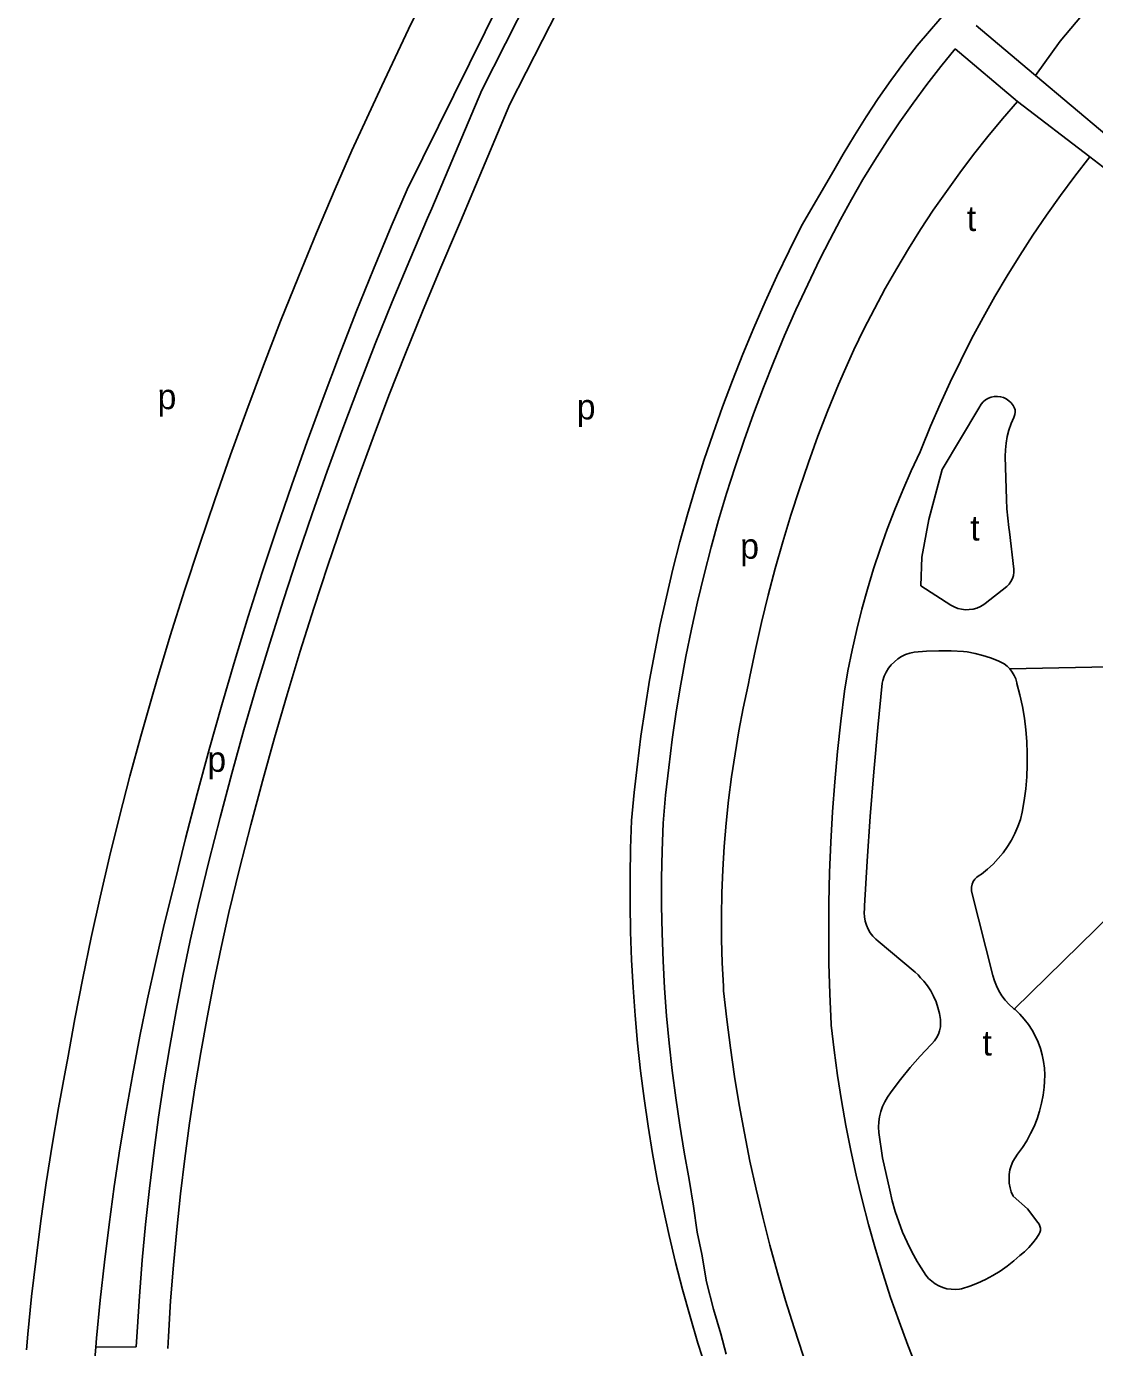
# Model space of a CAD drawing. Extents: x 161494 to 163033, y 383688 to 384862.
# Drawn here: x 161508.7 to 161678.1, y 384170.2 to 384379.7 of the extents above; entities that cross this region are included whole.
import ezdxf

# ---------------------------------------------------------------- set-up
doc = ezdxf.new("R2010")
doc.units = 0
doc.layers.add('BLT_Basislijn', color=7, linetype='Continuous')
doc.layers.add('BLT_Centroide', color=7, linetype='Continuous')

msp = doc.modelspace()

# ---------------------------------------------------------------- linework, layer by layer
at = {"layer": 'BLT_Basislijn'}
for p, q in [((161627.72, 384461.69), (161580.87, 384369.61)), ((161592.77, 384381.97), (161590.5, 384377.51)), ((161659.3, 384379.87), (161668.38, 384372.17)), ((161590.5, 384377.51), (161585.32, 384367.34)), ((161655.95, 384376.15), (161665.86, 384367.81)), ((161668.71, 384371.89), (161668.38, 384372.17)), ((161680, 384362.41), (161668.71, 384371.89)), ((161580.87, 384369.61), (161572.96, 384350.8)), ((161585.32, 384367.34), (161577.52, 384348.75)), ((161677.29, 384359), (161665.86, 384367.81)), ((161691.03, 384348.41), (161677.29, 384359)), ((161636.69, 384356.84), (161631.59, 384348.06)), ((161653.88, 384309.4), (161659.72, 384319.16)), ((161660.08, 384319.79), (161659.72, 384319.16)), ((161663.89, 384311.49), (161664.12, 384304.65)), ((161651.76, 384301.5), (161653.88, 384309.4)), ((161665.26, 384293.63), (161664.6, 384299.56)), ((161655.27, 384287.92), (161650.51, 384290.96)), ((161660.71, 384288.19), (161664.16, 384290.86)), ((161664.61, 384277.82), (161691.09, 384278.37)), ((161658.57, 384242.55), (161661.91, 384229.19)), ((161643.76, 384234.59), (161649.6, 384229.7)), ((161651.32, 384181.63), (161650.2, 384183.36)), ((161519.21, 384164.89), (161519.66, 384170.2)), ((161526.07, 384170.29), (161519.66, 384170.2))]:
    msp.add_line(p, q, dxfattribs=at)
for points in [[(161560.26, 384360.04), (161565.01, 384370.29), (161569.26, 384379.28), (161580.75, 384402.53), (161611.1, 384462.16)], [(161622.83, 384461.81), (161603.33, 384423.62), (161581.43, 384378.84), (161569.05, 384353.83)], [(161716.98, 384430.06), (161672.62, 384377.38), (161668.71, 384371.89)], [(161655.48, 384383.11), (161649.95, 384376.68), (161647.82, 384373.92), (161645.76, 384371.11), (161643.77, 384368.26), (161641.84, 384365.36), (161639.98, 384362.42), (161638.18, 384359.44), (161636.69, 384356.84)], [(161655.95, 384376.15), (161653.67, 384373.33), (161651.45, 384370.46), (161649.29, 384367.54), (161647.2, 384364.57), (161645.18, 384361.56), (161643.22, 384358.5), (161641.33, 384355.4), (161639.51, 384352.27), (161637.76, 384349.09), (161636.08, 384345.86)], [(161665.86, 384367.81), (161663.48, 384365.05), (161661.15, 384362.25), (161658.89, 384359.4), (161656.69, 384356.49), (161654.56, 384353.54), (161652.49, 384350.55), (161650.48, 384347.5), (161648.55, 384344.42), (161646.68, 384341.29), (161644.88, 384338.12), (161643.15, 384334.92), (161641.49, 384331.68), (161639.91, 384328.4), (161638.39, 384325.08), (161637.44, 384322.89)], [(161529.28, 384275.8), (161531.48, 384283.03), (161533.75, 384290.24), (161536.1, 384297.43), (161538.53, 384304.59), (161541.03, 384311.73), (161543.61, 384318.83), (161546.26, 384325.91), (161548.98, 384332.97), (161551.79, 384339.99), (161554.66, 384346.98), (161557.61, 384353.94), (161560.26, 384360.04)], [(161677.29, 384359), (161674.95, 384355.97), (161672.67, 384352.9), (161670.45, 384349.77), (161668.3, 384346.61), (161666.22, 384343.39), (161664.2, 384340.14), (161662.26, 384336.84), (161660.38, 384333.51), (161658.57, 384330.13), (161656.83, 384326.72), (161655.17, 384323.27), (161653.57, 384319.79), (161652.05, 384316.28), (161650.61, 384312.73), (161650.4, 384312.21)], [(161532.14, 384243.77), (161533.9, 384250.88), (161535.73, 384257.97), (161537.65, 384265.03), (161539.64, 384272.08), (161541.7, 384279.11), (161543.84, 384286.11), (161546.06, 384293.09), (161548.36, 384300.05), (161550.73, 384306.98), (161553.18, 384313.88), (161555.7, 384320.75), (161558.3, 384327.6), (161560.97, 384334.42), (161563.71, 384341.21), (161566.53, 384347.97), (161569.05, 384353.83)], [(161535.9, 384240.28), (161537.6, 384247.27), (161539.37, 384254.23), (161541.23, 384261.18), (161543.16, 384268.11), (161545.17, 384275.01), (161547.26, 384281.89), (161549.42, 384288.75), (161551.66, 384295.58), (161553.98, 384302.39), (161556.37, 384309.17), (161558.84, 384315.93), (161561.38, 384322.65), (161563.99, 384329.35), (161566.68, 384336.02), (161569.45, 384342.66), (161572.28, 384349.26), (161572.96, 384350.8)], [(161540.77, 384239.15), (161542.46, 384246.11), (161544.23, 384253.05), (161546.08, 384259.97), (161548.01, 384266.86), (161550.01, 384273.74), (161552.09, 384280.59), (161554.25, 384287.42), (161556.48, 384294.22), (161558.79, 384301), (161561.17, 384307.75), (161563.63, 384314.48), (161566.16, 384321.18), (161568.77, 384327.84), (161571.46, 384334.48), (161574.21, 384341.09), (161577.04, 384347.67), (161577.52, 384348.75)], [(161604.65, 384253.73), (161605.06, 384258.21), (161605.55, 384262.68), (161606.12, 384267.13), (161606.77, 384271.58), (161607.49, 384276.01), (161608.3, 384280.43), (161609.18, 384284.83), (161610.15, 384289.22), (161611.19, 384293.59), (161612.31, 384297.94), (161613.5, 384302.27), (161614.77, 384306.57), (161616.12, 384310.86), (161617.55, 384315.12), (161619.05, 384319.35), (161620.62, 384323.55), (161622.27, 384327.73), (161624, 384331.88), (161625.8, 384335.99), (161627.67, 384340.08), (161629.61, 384344.13), (161631.59, 384348.06)], [(161609.63, 384253.33), (161610.04, 384257.76), (161610.52, 384262.18), (161611.09, 384266.59), (161611.73, 384270.99), (161612.46, 384275.37), (161613.26, 384279.75), (161614.14, 384284.11), (161615.1, 384288.45), (161616.14, 384292.77), (161617.25, 384297.08), (161618.44, 384301.36), (161619.71, 384305.62), (161621.06, 384309.86), (161622.48, 384314.07), (161623.97, 384318.26), (161625.55, 384322.42), (161627.19, 384326.55), (161628.91, 384330.65), (161630.71, 384334.72), (161632.57, 384338.76), (161634.51, 384342.76), (161636.08, 384345.86)], [(161637.44, 384322.89), (161635.78, 384318.8), (161634.2, 384314.69), (161632.7, 384310.55), (161631.27, 384306.38), (161629.91, 384302.18), (161628.63, 384297.97), (161627.43, 384293.73), (161626.31, 384289.47), (161625.26, 384285.18), (161624.29, 384280.89), (161623.4, 384276.57), (161623.14, 384275.21)], [(161660.08, 384319.79), (161660.41, 384320.16), (161660.79, 384320.48), (161661.22, 384320.73), (161661.68, 384320.9), (161662.16, 384321), (161662.66, 384321.02), (161663.15, 384320.96), (161663.62, 384320.83), (161664.07, 384320.61), (161664.48, 384320.33), (161664.83, 384319.99), (161665.13, 384319.59), (161665.36, 384319.15), (161665.46, 384318.88)], [(161665.46, 384318.88), (161665.49, 384318.52), (161665.44, 384318.16), (161665.32, 384317.82), (161665.24, 384317.68)], [(161665.24, 384317.68), (161664.82, 384316.7), (161664.48, 384315.68), (161664.21, 384314.65), (161664.03, 384313.6), (161663.92, 384312.54), (161663.89, 384311.49)], [(161650.4, 384312.21), (161648.99, 384309.19), (161647.64, 384306.14), (161646.38, 384303.06), (161645.18, 384299.95), (161644.06, 384296.81), (161643.02, 384293.65), (161642.06, 384290.46), (161641.17, 384287.25), (161640.35, 384284.02), (161639.62, 384280.77), (161638.96, 384277.5), (161638.39, 384274.25)], [(161664.12, 384304.65), (161664.16, 384303.17), (161664.29, 384301.69), (161664.49, 384300.22), (161664.6, 384299.56)], [(161650.51, 384290.96), (161650.69, 384295.53), (161651.76, 384301.5)], [(161664.16, 384290.86), (161664.52, 384291.24), (161664.81, 384291.66), (161665.04, 384292.13), (161665.19, 384292.62), (161665.26, 384293.13), (161665.26, 384293.63)], [(161655.27, 384287.92), (161655.81, 384287.62), (161656.38, 384287.4), (161656.98, 384287.25), (161657.59, 384287.18), (161658.2, 384287.19), (161658.81, 384287.29), (161659.4, 384287.45), (161659.96, 384287.7), (161660.48, 384288.02), (161660.71, 384288.19)], [(161649.43, 384280.46), (161648.75, 384280.3), (161648.08, 384280.07), (161647.45, 384279.76), (161646.86, 384279.38), (161646.31, 384278.94), (161645.82, 384278.44), (161645.38, 384277.89), (161645.01, 384277.29), (161644.72, 384276.65), (161644.49, 384275.98), (161644.39, 384275.55)], [(161649.43, 384280.46), (161651.4, 384280.6), (161653.37, 384280.66), (161655.34, 384280.65), (161657.3, 384280.55), (161657.87, 384280.51)], [(161657.87, 384280.51), (161659.13, 384280.26), (161660.37, 384279.93), (161661.58, 384279.53), (161662.77, 384279.05), (161663.71, 384278.61)], [(161663.71, 384278.61), (161664.2, 384278.23), (161664.61, 384277.82)], [(161664.61, 384277.82), (161664.64, 384277.8), (161665.02, 384277.3), (161665.33, 384276.77), (161665.57, 384276.2), (161665.74, 384275.6), (161665.76, 384275.49)], [(161515.16, 384215.8), (161516.34, 384222.28), (161517.6, 384228.73), (161518.94, 384235.18), (161520.35, 384241.6), (161521.84, 384248.01), (161523.41, 384254.4), (161525.06, 384260.76), (161526.79, 384267.11), (161528.59, 384273.44), (161529.28, 384275.8)], [(161623.14, 384275.21), (161622.36, 384271.59), (161621.66, 384267.97), (161621.04, 384264.32), (161620.49, 384260.67), (161620.03, 384257), (161619.64, 384253.33), (161619.34, 384249.64), (161619.11, 384245.95), (161618.97, 384242.26), (161618.9, 384238.57), (161618.92, 384234.87), (161619.01, 384231.18), (161619.19, 384227.48), (161619.23, 384226.75)], [(161644.39, 384275.55), (161643.67, 384268.5), (161643.04, 384261.45), (161642.48, 384254.38), (161642, 384247.32), (161641.6, 384240.24), (161641.58, 384239.8)], [(161665.76, 384275.49), (161666.23, 384273.68), (161666.62, 384271.84), (161666.94, 384270), (161667.17, 384268.14), (161667.33, 384266.27), (161667.4, 384264.4), (161667.4, 384262.53), (161667.32, 384260.65), (161667.15, 384258.79), (161666.91, 384256.93), (161666.59, 384255.08), (161666.33, 384253.9)], [(161638.39, 384274.25), (161637.8, 384269.48), (161637.29, 384264.69), (161636.86, 384259.9), (161636.5, 384255.1), (161636.23, 384250.3), (161636.04, 384245.49), (161635.93, 384240.68), (161635.9, 384235.86), (161635.94, 384231.05), (161636.07, 384226.24), (161636.28, 384221.43), (161636.29, 384221.31)], [(161691.9, 384257.18), (161686.54, 384250.54), (161682.39, 384248.02), (161680.87, 384245.24), (161684.08, 384244.03), (161683.48, 384241.66), (161665.34, 384223.84)], [(161666.33, 384253.9), (161665.92, 384252.78), (161665.44, 384251.68), (161664.88, 384250.63), (161664.25, 384249.61), (161663.56, 384248.64), (161662.8, 384247.71), (161661.98, 384246.84), (161661.11, 384246.03), (161660.15, 384245.24)], [(161604.65, 384253.73), (161604.49, 384249.32), (161604.41, 384244.9), (161604.4, 384240.49), (161604.48, 384236.07), (161604.64, 384231.65), (161604.88, 384227.24), (161605.2, 384222.83), (161605.59, 384218.43), (161606.07, 384214.03), (161606.63, 384209.65), (161607.26, 384205.28), (161607.98, 384200.92), (161608.77, 384196.57), (161609.64, 384192.24), (161610.59, 384187.92), (161611.62, 384183.62), (161612.73, 384179.34), (161613.91, 384175.09), (161615.17, 384170.85), (161616.51, 384166.64)], [(161609.63, 384253.33), (161609.48, 384248.96), (161609.4, 384244.6), (161609.4, 384240.23), (161609.48, 384235.86), (161609.64, 384231.5), (161609.88, 384227.13), (161610.2, 384222.78), (161610.6, 384218.43), (161611.08, 384214.09), (161611.64, 384209.76), (161612.28, 384205.43), (161613, 384201.13), (161613.79, 384196.83), (161614.44, 384192.58), (161615.04, 384188.44), (161615.76, 384184.96), (161616.53, 384180.56), (161617.61, 384176.24), (161618.81, 384172.34), (161619.65, 384169.1)], [(161519.66, 384170.2), (161519.78, 384171.66), (161520.37, 384177.68), (161521.03, 384183.69), (161521.77, 384189.69), (161522.59, 384195.68), (161523.48, 384201.66), (161524.46, 384207.63), (161525.52, 384213.59), (161526.65, 384219.53), (161527.87, 384225.45), (161529.16, 384231.36), (161530.53, 384237.25), (161531.98, 384243.12), (161532.14, 384243.77)], [(161660.15, 384245.24), (161659.74, 384245.04), (161659.38, 384244.76), (161659.08, 384244.43), (161658.83, 384244.05), (161658.66, 384243.63), (161658.57, 384243.18), (161658.55, 384242.73), (161658.57, 384242.55)], [(161535.9, 384240.28), (161534.65, 384234.71), (161533.49, 384229.13), (161532.41, 384223.54), (161531.4, 384217.93), (161530.47, 384212.3), (161529.62, 384206.67), (161528.86, 384201.02), (161528.17, 384195.36), (161527.56, 384189.69), (161527.02, 384184.02), (161526.57, 384178.33), (161526.2, 384172.64), (161526.07, 384170.29)], [(161540.77, 384239.15), (161539.53, 384233.62), (161538.38, 384228.08), (161537.3, 384222.52), (161536.3, 384216.94), (161535.38, 384211.35), (161534.54, 384205.75), (161533.78, 384200.13), (161533.1, 384194.51), (161532.5, 384188.88), (161531.98, 384183.24), (161531.53, 384177.59), (161531.17, 384171.93), (161531.07, 384170.02)], [(161641.58, 384239.8), (161641.54, 384239.13), (161641.58, 384238.45), (161641.69, 384237.79), (161641.89, 384237.14), (161642.16, 384236.52), (161642.5, 384235.94), (161642.91, 384235.4), (161643.38, 384234.91), (161643.76, 384234.59)], [(161650.48, 384228.82), (161650.07, 384229.29), (161649.6, 384229.7)], [(161653.61, 384222.21), (161653.46, 384223.16), (161653.23, 384224.09), (161652.92, 384224.99), (161652.54, 384225.87), (161652.09, 384226.71), (161651.57, 384227.51), (161650.99, 384228.27), (161650.48, 384228.82)], [(161661.91, 384229.19), (161662.17, 384228.34), (161662.49, 384227.51), (161662.89, 384226.72), (161663.36, 384225.96), (161663.9, 384225.25), (161664.5, 384224.59), (161665.15, 384223.99), (161665.34, 384223.84)], [(161619.23, 384226.75), (161619.73, 384222.21), (161620.31, 384217.69), (161620.96, 384213.17), (161621.7, 384208.67), (161622.52, 384204.18), (161623.41, 384199.71), (161624.38, 384195.25), (161625.43, 384190.81), (161626.56, 384186.39), (161627.77, 384181.99), (161629.05, 384177.61), (161630.41, 384173.26), (161631.84, 384168.92), (161633.36, 384164.62), (161634.94, 384160.34), (161636.6, 384156.09), (161638.09, 384152.46)], [(161665.34, 384223.84), (161665.45, 384223.75)], [(161665.45, 384223.75), (161666.21, 384223.02), (161666.92, 384222.23), (161667.57, 384221.39), (161668.15, 384220.5), (161668.67, 384219.57), (161669.11, 384218.6), (161669.48, 384217.61), (161669.77, 384216.59), (161669.98, 384215.55), (161670.12, 384214.49), (161670.17, 384213.43), (161670.15, 384212.37)], [(161636.29, 384221.31), (161636.75, 384217.31), (161637.3, 384213.32), (161637.92, 384209.34), (161638.62, 384205.37), (161639.4, 384201.42), (161640.26, 384197.48), (161641.2, 384193.56), (161642.22, 384189.66), (161643.31, 384185.78), (161644.48, 384181.93), (161645.72, 384178.09), (161647.05, 384174.29), (161648.44, 384170.51), (161649.91, 384166.76), (161651.46, 384163.03), (161653.09, 384159.31)], [(161653.61, 384222.21), (161653.65, 384221.61), (161653.61, 384221), (161653.48, 384220.41), (161653.29, 384219.84), (161653.02, 384219.3), (161652.68, 384218.79), (161652.27, 384218.34), (161652.09, 384218.17)], [(161652.09, 384218.17), (161650.43, 384216.39), (161648.84, 384214.55), (161647.3, 384212.67), (161645.83, 384210.73), (161645.21, 384209.87)], [(161508.66, 384169.81), (161508.88, 384172.26), (161509.49, 384178.27), (161510.19, 384184.28), (161510.96, 384190.27), (161511.81, 384196.26), (161512.74, 384202.23), (161513.75, 384208.19), (161514.84, 384214.13), (161515.16, 384215.8)], [(161665.85, 384200.83), (161666.61, 384201.87), (161667.3, 384202.95), (161667.92, 384204.08), (161668.47, 384205.24), (161668.94, 384206.44), (161669.34, 384207.66), (161669.67, 384208.91), (161669.91, 384210.17), (161670.08, 384211.44), (161670.15, 384212.37)], [(161645.21, 384209.87), (161644.79, 384209.14), (161644.44, 384208.38), (161644.16, 384207.59), (161643.96, 384206.77), (161643.84, 384205.94), (161643.79, 384205.1), (161643.83, 384204.27)], [(161643.83, 384204.27), (161644.45, 384200.26), (161645.59, 384195.1)], [(161665.14, 384194.18), (161664.86, 384194.83), (161664.66, 384195.51), (161664.54, 384196.21), (161664.5, 384196.91), (161664.53, 384197.62), (161664.65, 384198.32), (161664.84, 384198.99), (161665.11, 384199.65), (161665.46, 384200.27), (161665.85, 384200.83)], [(161645.59, 384195.1), (161645.98, 384193.41), (161646.45, 384191.74), (161647, 384190.1), (161647.62, 384188.48), (161648.32, 384186.89), (161649.08, 384185.34), (161649.92, 384183.82), (161650.2, 384183.36)], [(161669.05, 384190), (161667.42, 384192.14), (161665.14, 384194.18)], [(161669.05, 384190), (161669.26, 384189.73), (161669.41, 384189.41), (161669.48, 384189.07), (161669.48, 384188.72), (161669.39, 384188.38), (161669.29, 384188.18)], [(161666.2, 384184.74), (161666.95, 384185.36), (161667.65, 384186.03), (161668.3, 384186.75), (161668.88, 384187.53), (161669.29, 384188.18)], [(161656.98, 384179.47), (161658.27, 384179.89), (161659.52, 384180.38), (161660.75, 384180.95), (161661.94, 384181.58), (161663.09, 384182.29), (161664.19, 384183.06), (161665.25, 384183.9), (161666.2, 384184.74)], [(161651.32, 384181.63), (161651.75, 384181.12), (161652.25, 384180.66), (161652.79, 384180.26), (161653.38, 384179.93), (161654, 384179.68), (161654.65, 384179.49), (161655.31, 384179.39), (161655.99, 384179.36), (161656.66, 384179.42), (161656.98, 384179.47)]]:
    msp.add_lwpolyline(points, dxfattribs=at)

# ---------------------------------------------------------------- texts
at = {"layer": 'BLT_Centroide'}
for s, p in [('t', (161657.81, 384347.25)), ('p', (161529.46, 384318.99)), ('p', (161595.94, 384317.37)), ('t', (161658.36, 384298.15)), ('p', (161621.87, 384295.27)), ('p', (161537.35, 384261.47)), ('t', (161660.28, 384216.47))]:
    msp.add_text(s, height=4, dxfattribs=at).set_placement(p)

doc.saveas('drawing.dxf')
